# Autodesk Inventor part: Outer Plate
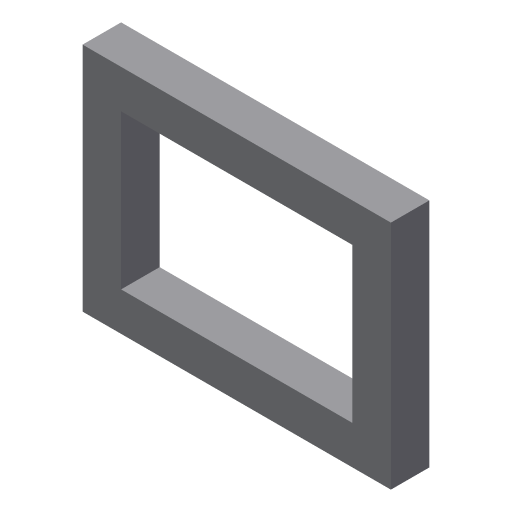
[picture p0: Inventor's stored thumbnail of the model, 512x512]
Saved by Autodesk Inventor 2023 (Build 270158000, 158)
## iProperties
Created: 2010-04
Part Number: Outer Plate
Document SubType Name: Modeling
Designer: CADSoft
Density: 1 g/cm^3
Material: Generic
Appearance: Default
Author: CADSoft
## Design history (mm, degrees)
sketch "Sketch1"
  geometry: L1 (-40, 30)-(40, 30); L2 (40, 30)-(40, -30); L3 (40, -30)-(-40, -30); L4 (-40, -30)-(-40, 30); L5 (-30, 20)-(30, 20); L6 (30, 20)-(30, -20); L7 (30, -20)-(-30, -20); L8 (-30, -20)-(-30, 20); 1 further point
  constraints: 16 end point, 4 parallel, 2 horizontal, 2 perpendicular
  dimensions: "d0" = 80 distance of L1.start L1.end; "d1" = 60 distance of L5.start L5.end; "d2" = 10 distance between parallel lines of L4 L8; "d3" = 10 distance between parallel lines of L1 L5; "d4" = 40 distance of L7.end L5.start; "d5" = 60 distance of L3.end L1.start
extrude "Extrusion1" new body sketch "Sketch1" distance "d8" = 10; taper "d9" = 0 deg
body "Solid1"
